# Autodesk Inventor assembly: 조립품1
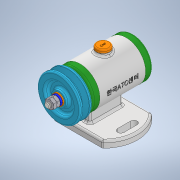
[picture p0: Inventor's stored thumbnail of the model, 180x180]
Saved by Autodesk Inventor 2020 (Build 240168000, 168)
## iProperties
Created: 2021-09
Part Number: 조립품1
Document SubType Name: Assembly
Designer: Administrator
Author: Administrator
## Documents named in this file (14)
- C:\Users\Administrator\Desktop\710906V1013\조립품1.iam
- C:\Users\Administrator\Desktop\710906V1013\본체.ipt
- C:\Users\Administrator\Desktop\710906V1013\베어링 15x32x9.ipt
- C:\Users\Administrator\Desktop\710906V1013\앞커버.ipt
- C:\Users\Administrator\Desktop\710906V1013\뒤커버.ipt
- C:\Users\Administrator\Desktop\710906V1013\캡.ipt
- C:\Users\Administrator\Desktop\710906V1013\오일 실 15x25x7.ipt
- C:\Users\Administrator\Desktop\710906V1013\볼트 M4x12.ipt
- C:\Users\Administrator\Desktop\710906V1013\축.ipt
- C:\Users\Administrator\Desktop\710906V1013\키 3x3.ipt
- C:\Users\Administrator\Desktop\710906V1013\V벨트풀리.ipt
- C:\Users\Administrator\Desktop\710906V1013\와셔 8x17.ipt
- C:\Users\Administrator\Desktop\710906V1013\스프링와셔 8.ipt
- C:\Users\Administrator\Desktop\710906V1013\너트 M8.ipt
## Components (1 placed, 1 different names)
1. V벨트풀리:1
